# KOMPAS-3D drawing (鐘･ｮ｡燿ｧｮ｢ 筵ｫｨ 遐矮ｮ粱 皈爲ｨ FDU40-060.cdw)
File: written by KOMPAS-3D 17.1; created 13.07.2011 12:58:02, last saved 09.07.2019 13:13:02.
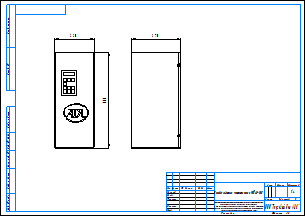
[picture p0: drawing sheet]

Title block, sheet 1: name: Преобразователи частоты серии FDU40-060; scale: 1:4; sheets: 1; sheet format: A3; stored path: \\adlc.lan\data\АДЛ_ПКД\3D-модели\Поставщики\Оборудование Emotron\Преобразователи частоты\Серия FDU 2.0\KOMPAS 2D\Преобразователи частоты серии FDU40-060.cdw

Views: Спереди 1
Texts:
  Рама для чертежей
  Лит-Масса-Масштаб
  Материал-Предприятие
  Масштаб
  Изм.
  Лист
  № докум.
  Подп.
  Дата
  Лит.
  Разраб.
  Пров.
  Т.контр.
  Листов
  Внимание! Данный продукт является объектом авторского права ООО «Торговый Дом АДЛ».
  Запрещается изменение, копирование, распространение
  (в том числе путем копирования на другие сайты и ресурсы в Интернете)
  или любое иное использование информации и объектов без предварительного
  согласия правообладателя (ООО «Торговый Дом АДЛ»).
  Н.контр.
  Утв.
  ООО "Торговый дом АДЛ"
  Изменение
  Номер документа
  Подпись
  Обозначение документа
  Наименование изделия
  Масса изделия по ГОСТ 2.109-73
  Порядковый номер листа
  Общее количество листов в документе
  Характер работы, выполненной лицом, подписавшим документ
  Наименование или индекс предприятия, выпускающего документ
  Инв. № подл.
  Подп. и дата
  Взам. инв. №
  Инв. № дубл.
  Инвентарный номер подлинника по ГОСТ 2.501-68
  Подпись принявшего подлинник в отдел технической документации
  Инвентарный номер подлинника, взамен которого выпущен данный подлинник
  Инвентарный номер дубликата по ГОСТ 2.502-68
  Подпись принявшего дубликат в отдел технической документации
  Справ. №
  Перв. примен.
  Обозначение документа, взамен или на основании которого выпущен данный документ
  Обозначение документа, в котором впервые записан данный документ
  Подпись лица, копировавшего чертеж
  Обозначение формата листа
  !Рама для чертежа
Dimensions and other numbers on the sheet: 220; 270; 530; 1:4; 1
